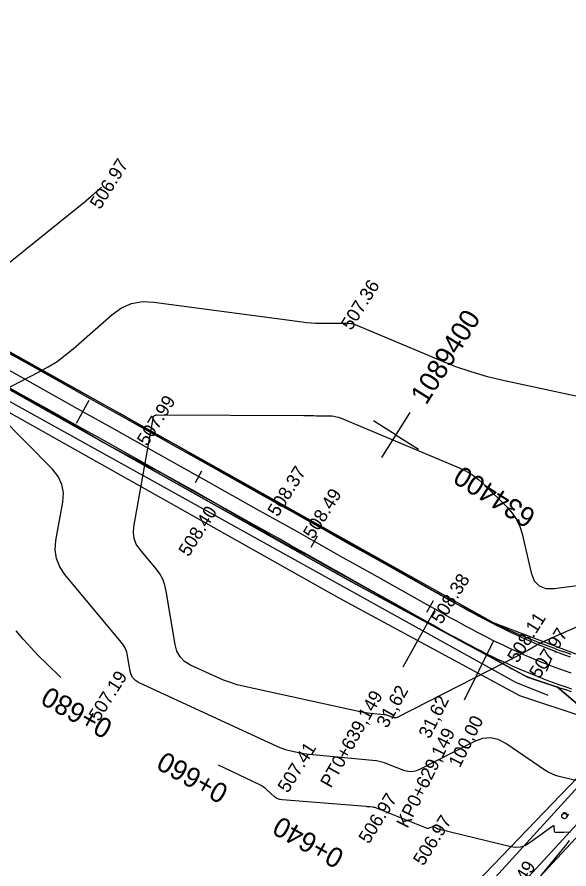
# Model space of a CAD drawing. Extents: x -636600 to -628587, y -1090963 to -1085869.
# Drawn here: x -629764.9 to -629681.7, y -1090120.7 to -1089992.4 of the extents above; entities that cross this region are included whole.
import ezdxf

# ---------------------------------------------------------------- set-up
doc = ezdxf.new("R2010")
doc.units = 0
for name, color, linetype in [('01_PARCELY_NÁVRH_PC', 7, 'Continuous'), ('06_ÚSES_IP_NAVRH', 7, 'Continuous'), ('42', 7, 'Continuous'), ('43', 7, 'Continuous'), ('Ex_Major Contours', 7, 'Continuous'), ('Ex_Minor Contours', 7, 'Continuous'), ('HEKTOMETRY100', 7, 'Continuous'), ('HEKTOMETRY20', 7, 'Continuous'), ('HL_BODY', 7, 'Continuous'), ('koty_vše', 7, 'Continuous'), ('POLOMERY', 7, 'Continuous'), ('situace_osa', 7, 'Continuous'), ('situace_těleso', 7, 'Continuous'), ('situace_vozovka', 7, 'Continuous'), ('síť křížků', 7, 'Continuous')]:
    doc.layers.add(name, color=color, linetype=linetype)

msp = doc.modelspace()

# ---------------------------------------------------------------- linework, layer by layer
at = {"layer": '01_PARCELY_NÁVRH_PC'}
for points in [[(-629590.44, -1089927.9), (-629610.34, -1089962.86), (-629611.05, -1089962.47), (-629613.94, -1089967.55), (-629651.31, -1090060.76), (-629656.7, -1090071.62), (-629663.92, -1090084.26), (-629669.51, -1090092.1), (-629671.7, -1090096.43), (-629679.1, -1090105.56), (-629740.1, -1090168.89), (-629745.82, -1090175.94), (-629753.08, -1090187.33), (-629759.69, -1090209.29), (-629763.83, -1090224.9)], [(-629757.08, -1090224.9), (-629756.4, -1090222.95), (-629754.36, -1090212.07), (-629743.98, -1090191.89), (-629738.43, -1090182.38), (-629727.31, -1090166.03), (-629671.82, -1090106.56), (-629662.5, -1090094.94), (-629652.06, -1090078.29), (-629645.47, -1090064.84), (-629624.55, -1090013.22), (-629617.14, -1089992.88), (-629607.22, -1089968.87), (-629597.44, -1089950.1), (-629584.51, -1089927.9)], [(-629847.27, -1090002.89), (-629714.93, -1090077.19), (-629687.95, -1090091.78), (-629683.43, -1090093.29), (-629680.05, -1090096.13), (-629678.2, -1090100.3), (-629678.37, -1090104.71), (-629671.7, -1090096.43), (-629669.51, -1090092.1), (-629668.44, -1090090.6), (-629674.53, -1090090.62), (-629693.09, -1090083.59), (-629847.27, -1089997.35)], [(-629847.27, -1090006.33), (-629716.38, -1090079.82), (-629689.14, -1090094.54), (-629679.3, -1090097.83), (-629680.05, -1090096.13), (-629683.43, -1090093.29), (-629687.95, -1090091.78), (-629714.93, -1090077.19), (-629847.27, -1090002.89)]]:
    msp.add_lwpolyline(points, dxfattribs=at)
at = {"layer": '06_ÚSES_IP_NAVRH'}
msp.add_lwpolyline([(-629684.85, -1090094.55), (-629689.69, -1090092.6), (-629772.39, -1090046.76), (-629847.27, -1090004.61)], dxfattribs=at)
at = {"layer": '42'}
for p, q in [((-629707.87, -1090138.35), (-629674.34, -1090101.71)), ((-629705.08, -1090140.65), (-629671.28, -1090103.86))]:
    msp.add_line(p, q, dxfattribs=at)
at = {"layer": '43'}
for p, q in [((-629682, -1090112.83), (-629681.74, -1090112.41)), ((-629682.05, -1090112.92), (-629682, -1090112.83))]:
    msp.add_line(p, q, dxfattribs=at)
msp.add_circle((-629682.39, -1090112.7), 0.4, dxfattribs=at)
msp.add_arc((-629682.34, -1090112.62), 0.4, 317.5323, 155.0179, dxfattribs=at)
at = {"layer": 'Ex_Major Contours'}
for points in [[(-629767.09, -1090048.68), (-629761.54, -1090045.82), (-629760.18, -1090045.06), (-629758.87, -1090044.23), (-629757.62, -1090043.32), (-629756.42, -1090042.33), (-629750.58, -1090037.21), (-629749.16, -1090036.19), (-629747.63, -1090035.53), (-629746, -1090035.24), (-629744.25, -1090035.3), (-629721.91, -1090038.3), (-629721.24, -1090038.38), (-629720.58, -1090038.44), (-629719.91, -1090038.47), (-629719.24, -1090038.49), (-629715.43, -1090038.5), (-629715.33, -1090038.5), (-629715.22, -1090038.5), (-629715.12, -1090038.5), (-629715.01, -1090038.5), (-629714.59, -1090038.51), (-629714.49, -1090038.51), (-629714.39, -1090038.53), (-629714.29, -1090038.55), (-629714.19, -1090038.59), (-629701.02, -1090044.12), (-629698.78, -1090045), (-629696.5, -1090045.78), (-629694.19, -1090046.45), (-629691.85, -1090047.01), (-629678.57, -1090049.89)], [(-629680.26, -1090107.45), (-629683.18, -1090106.73), (-629683.74, -1090106.57), (-629684.29, -1090106.35), (-629684.81, -1090106.09), (-629685.32, -1090105.78), (-629691.19, -1090101.77), (-629692.35, -1090101.17), (-629693.52, -1090100.92), (-629694.72, -1090101.02), (-629695.94, -1090101.47), (-629704.32, -1090105.74), (-629704.88, -1090105.96), (-629705.44, -1090106.05), (-629706.01, -1090106.01), (-629706.59, -1090105.84), (-629708.91, -1090104.91), (-629709.5, -1090104.7), (-629710.09, -1090104.53), (-629710.7, -1090104.4), (-629711.32, -1090104.32), (-629720.84, -1090103.41), (-629721.24, -1090103.36), (-629721.65, -1090103.31), (-629722.05, -1090103.24), (-629722.45, -1090103.16), (-629724.05, -1090102.81), (-629724.44, -1090102.71), (-629724.83, -1090102.59), (-629725.21, -1090102.45), (-629725.59, -1090102.29), (-629746.58, -1090092.57), (-629747.06, -1090092.28), (-629747.44, -1090091.91), (-629747.7, -1090091.45), (-629747.85, -1090090.9), (-629748.23, -1090088.57), (-629748.36, -1090088), (-629748.56, -1090087.46), (-629748.83, -1090086.96), (-629749.18, -1090086.49), (-629757.68, -1090076.32), (-629758.46, -1090075.16), (-629758.95, -1090073.91), (-629759.14, -1090072.59), (-629759.03, -1090071.19), (-629758, -1090065.43), (-629757.9, -1090064.04), (-629758.13, -1090062.75), (-629758.67, -1090061.56), (-629759.55, -1090060.48), (-629767.66, -1090052.32)]]:
    msp.add_lwpolyline(points, dxfattribs=at)
at = {"layer": 'Ex_Minor Contours'}
for points in [[(-629772.71, -1090034.67), (-629755.35, -1090020.73), (-629754.94, -1090020.39), (-629754.53, -1090020.05), (-629754.12, -1090019.71), (-629753.72, -1090019.36), (-629752.15, -1090017.99)], [(-629679.2, -1090083.64), (-629685.47, -1090086.41), (-629685.79, -1090086.56), (-629686.1, -1090086.71), (-629686.41, -1090086.87), (-629686.71, -1090087.05), (-629687.9, -1090087.75), (-629688.2, -1090087.93), (-629688.51, -1090088.1), (-629688.81, -1090088.26), (-629689.12, -1090088.42), (-629707.6, -1090097.85), (-629707.76, -1090097.91), (-629707.91, -1090097.93), (-629708.07, -1090097.92), (-629708.23, -1090097.87), (-629708.87, -1090097.62), (-629709.03, -1090097.56), (-629709.2, -1090097.51), (-629709.37, -1090097.48), (-629709.54, -1090097.45), (-629711.59, -1090097.26), (-629711.99, -1090097.21), (-629712.39, -1090097.16), (-629712.79, -1090097.09), (-629713.18, -1090097.01), (-629730.62, -1090093.19), (-629731.69, -1090092.93), (-629732.73, -1090092.61), (-629733.75, -1090092.24), (-629734.76, -1090091.8), (-629738.74, -1090089.96), (-629739.63, -1090089.42), (-629740.32, -1090088.73), (-629740.8, -1090087.88), (-629741.08, -1090086.88), (-629742.39, -1090078.84), (-629742.6, -1090077.92), (-629742.93, -1090077.05), (-629743.37, -1090076.23), (-629743.93, -1090075.46), (-629746.4, -1090072.51), (-629746.92, -1090071.75), (-629747.24, -1090070.93), (-629747.36, -1090070.06), (-629747.29, -1090069.14), (-629744.3, -1090052.52), (-629744.29, -1090052.47), (-629744.27, -1090052.44), (-629744.24, -1090052.41), (-629744.19, -1090052.39), (-629744.01, -1090052.33), (-629743.97, -1090052.31), (-629743.92, -1090052.3), (-629743.87, -1090052.3), (-629743.83, -1090052.3), (-629721.65, -1090052.4), (-629721.18, -1090052.4), (-629720.71, -1090052.4), (-629720.23, -1090052.4), (-629719.76, -1090052.41), (-629717.86, -1090052.41), (-629717.4, -1090052.44), (-629716.94, -1090052.51), (-629716.48, -1090052.62), (-629716.04, -1090052.78), (-629698.34, -1090060.22), (-629697.27, -1090060.73), (-629696.26, -1090061.33), (-629695.31, -1090062.03), (-629694.43, -1090062.83), (-629691.02, -1090066.2), (-629690.24, -1090067.08), (-629689.61, -1090068.04), (-629689.12, -1090069.09), (-629688.77, -1090070.21), (-629687.38, -1090076.08), (-629686.92, -1090077.26), (-629686.2, -1090078.04), (-629685.21, -1090078.44), (-629683.95, -1090078.45), (-629670.43, -1090076.66)], [(-629758.31, -1090091.84), (-629760.47, -1090089.74), (-629761.66, -1090088.56), (-629762.81, -1090087.34), (-629763.93, -1090086.1), (-629765.02, -1090084.83)], [(-629681.49, -1090115.13), (-629682.46, -1090115.16), (-629682.6, -1090115.16), (-629682.74, -1090115.17), (-629682.89, -1090115.17), (-629683.03, -1090115.17), (-629683.61, -1090115.18), (-629683.73, -1090115.17), (-629683.82, -1090115.12), (-629683.87, -1090115.03), (-629683.9, -1090114.91), (-629683.92, -1090114.35), (-629683.94, -1090114.24), (-629683.98, -1090114.19), (-629684.05, -1090114.18), (-629684.15, -1090114.24), (-629687.71, -1090116.8), (-629688.36, -1090117.17), (-629689.03, -1090117.38), (-629689.74, -1090117.44), (-629690.48, -1090117.33), (-629701.4, -1090114.67), (-629701.48, -1090114.64), (-629701.57, -1090114.61), (-629701.65, -1090114.57), (-629701.72, -1090114.52), (-629702.02, -1090114.32), (-629702.1, -1090114.28), (-629702.17, -1090114.26), (-629702.25, -1090114.27), (-629702.33, -1090114.3), (-629702.76, -1090114.52), (-629702.86, -1090114.56), (-629702.95, -1090114.57), (-629703.05, -1090114.56), (-629703.16, -1090114.53), (-629710.71, -1090111.5), (-629710.83, -1090111.45), (-629710.95, -1090111.42), (-629711.08, -1090111.39), (-629711.21, -1090111.37), (-629711.73, -1090111.32), (-629711.86, -1090111.31), (-629711.99, -1090111.3), (-629712.12, -1090111.29), (-629712.25, -1090111.28), (-629724.92, -1090110.28), (-629725.26, -1090110.22), (-629725.58, -1090110.11), (-629725.87, -1090109.95), (-629726.14, -1090109.74), (-629727.17, -1090108.78), (-629727.44, -1090108.55), (-629727.72, -1090108.34), (-629728.01, -1090108.16), (-629728.32, -1090107.99), (-629734.53, -1090105.02)], [(-629680.94, -1090125.5), (-629682.58, -1090124.35), (-629682.93, -1090124.11), (-629683.29, -1090123.87), (-629683.65, -1090123.64), (-629684.02, -1090123.41), (-629685.49, -1090122.51), (-629685.78, -1090122.27), (-629685.9, -1090122.01), (-629685.87, -1090121.72), (-629685.68, -1090121.4), (-629681.97, -1090116.87), (-629681.85, -1090116.71), (-629681.74, -1090116.55), (-629681.64, -1090116.38)]]:
    msp.add_lwpolyline(points, dxfattribs=at)
at = {"layer": 'HEKTOMETRY100'}
msp.add_lwpolyline([(-629755.95, -1090053.56), (-629754, -1090050.07)], dxfattribs=at)
at = {"layer": 'HEKTOMETRY20'}
for points in [[(-629738.01, -1090062.46), (-629737.03, -1090060.72)], [(-629720.56, -1090072.23), (-629719.58, -1090070.49)], [(-629703.11, -1090082), (-629702.13, -1090080.26)], [(-629685.06, -1090090.9), (-629684.34, -1090089.04)]]:
    msp.add_lwpolyline(points, dxfattribs=at)
at = {"layer": 'HL_BODY'}
for points in [[(-629701.88, -1090081.55), (-629706.76, -1090090.27)], [(-629693.07, -1090086.29), (-629697.52, -1090095.24)]]:
    msp.add_lwpolyline(points, dxfattribs=at)
at = {"layer": 'POLOMERY'}
for points in [[(-629701.88, -1090081.55), (-629706.76, -1090090.27)], [(-629693.07, -1090086.29), (-629697.52, -1090095.24)]]:
    msp.add_lwpolyline(points, dxfattribs=at)
at = {"layer": 'situace_osa'}
msp.add_lwpolyline([(-629681.39, -1090091.19), (-629682.24, -1090090.89), (-629683.09, -1090090.58), (-629683.94, -1090090.26), (-629684.7, -1090089.97), (-629684.79, -1090089.94), (-629685.63, -1090089.61), (-629686.47, -1090089.27), (-629687.31, -1090088.92), (-629688.14, -1090088.57), (-629688.97, -1090088.21), (-629689.32, -1090088.05), (-629689.8, -1090087.84), (-629690.62, -1090087.46), (-629691.44, -1090087.08), (-629692.26, -1090086.68), (-629693.07, -1090086.29), (-629693.83, -1090085.9), (-629693.89, -1090085.88), (-629694.69, -1090085.46), (-629695.5, -1090085.04), (-629696.3, -1090084.62), (-629697.1, -1090084.19), (-629697.9, -1090083.75), (-629698.25, -1090083.56), (-629698.7, -1090083.32), (-629699.5, -1090082.88), (-629700.29, -1090082.43), (-629701.08, -1090081.99), (-629701.88, -1090081.55), (-629702.62, -1090081.13), (-629706.98, -1090078.69), (-629711.35, -1090076.25), (-629715.71, -1090073.8), (-629720.07, -1090071.36), (-629722.64, -1090069.92), (-629724.43, -1090068.92), (-629728.8, -1090066.47), (-629733.16, -1090064.03), (-629737.52, -1090061.59), (-629741.88, -1090059.15), (-629746.25, -1090056.7), (-629750.61, -1090054.26), (-629754.97, -1090051.82), (-629759.33, -1090049.38), (-629763.7, -1090046.93), (-629768.06, -1090044.49)], dxfattribs=at)
at = {"layer": 'situace_těleso'}
for points in [[(-629681.35, -1090088.38), (-629682.18, -1090088.09), (-629683.01, -1090087.8), (-629683.76, -1090087.52), (-629683.84, -1090087.49), (-629684.66, -1090087.17), (-629685.48, -1090086.85), (-629686.31, -1090086.54), (-629687.13, -1090086.22), (-629687.96, -1090085.9), (-629688.3, -1090085.76), (-629688.78, -1090085.57), (-629689.59, -1090085.23), (-629690.39, -1090084.86), (-629691.2, -1090084.49), (-629692, -1090084.12), (-629692.75, -1090083.76), (-629692.8, -1090083.73), (-629693.6, -1090083.34), (-629694.4, -1090082.94), (-629695.19, -1090082.54), (-629695.99, -1090082.13), (-629696.79, -1090081.71), (-629697.13, -1090081.53), (-629697.58, -1090081.29), (-629698.38, -1090080.87), (-629699.18, -1090080.44), (-629699.98, -1090080.01), (-629700.77, -1090079.58), (-629701.51, -1090079.15), (-629705.85, -1090076.67), (-629710.19, -1090074.18), (-629714.53, -1090071.7), (-629718.9, -1090069.27), (-629721.49, -1090067.88), (-629723.28, -1090066.85), (-629727.66, -1090064.45), (-629732.02, -1090062), (-629736.35, -1090059.5), (-629740.68, -1090056.99), (-629745.06, -1090054.58), (-629749.4, -1090052.1), (-629753.76, -1090049.66), (-629758.15, -1090047.26), (-629762.54, -1090044.87), (-629766.93, -1090042.47)], [(-629769.17, -1090046.47), (-629764.84, -1090048.97), (-629760.47, -1090051.4), (-629756.12, -1090053.87), (-629751.84, -1090056.46), (-629747.44, -1090058.83), (-629742.99, -1090061.12), (-629738.65, -1090063.6), (-629734.26, -1090066.01), (-629729.93, -1090068.5), (-629725.62, -1090071.04), (-629723.84, -1090072.07), (-629721.19, -1090073.35), (-629716.83, -1090075.82), (-629712.45, -1090078.22), (-629708.11, -1090080.7), (-629703.77, -1090083.19), (-629703.04, -1090083.62), (-629702.24, -1090084.05), (-629701.43, -1090084.48), (-629700.62, -1090084.91), (-629699.81, -1090085.33), (-629699.35, -1090085.57), (-629699, -1090085.76), (-629698.18, -1090086.18), (-629697.37, -1090086.61), (-629696.56, -1090087.06), (-629695.75, -1090087.5), (-629694.93, -1090087.94), (-629694.88, -1090087.97), (-629694.12, -1090088.4), (-629693.31, -1090088.85), (-629692.49, -1090089.29), (-629691.68, -1090089.75), (-629690.87, -1090090.2), (-629690.39, -1090090.46), (-629690.05, -1090090.65), (-629689.22, -1090091.08), (-629688.39, -1090091.51), (-629687.53, -1090091.87), (-629686.66, -1090092.18), (-629685.78, -1090092.49), (-629685.69, -1090092.53), (-629684.9, -1090092.8), (-629684.01, -1090093.09), (-629683.13, -1090093.38), (-629682.24, -1090093.66), (-629681.35, -1090093.93)]]:
    msp.add_lwpolyline(points, dxfattribs=at)
at = {"layer": 'situace_vozovka'}
for points in [[(-629681.48, -1090088.77), (-629682.32, -1090088.47), (-629683.15, -1090088.16), (-629683.89, -1090087.87), (-629683.97, -1090087.84), (-629684.8, -1090087.52), (-629685.62, -1090087.18), (-629686.44, -1090086.85), (-629687.25, -1090086.5), (-629688.06, -1090086.15), (-629688.4, -1090086), (-629688.87, -1090085.79), (-629689.68, -1090085.42), (-629690.48, -1090085.04), (-629691.28, -1090084.66), (-629692.07, -1090084.27), (-629692.82, -1090083.9), (-629692.87, -1090083.87), (-629693.66, -1090083.47), (-629694.45, -1090083.05), (-629695.24, -1090082.63), (-629696.03, -1090082.21), (-629696.82, -1090081.78), (-629697.17, -1090081.59), (-629697.61, -1090081.35), (-629698.4, -1090080.91), (-629699.19, -1090080.47), (-629699.99, -1090080.03), (-629700.78, -1090079.58), (-629701.52, -1090079.17), (-629705.88, -1090076.73), (-629710.25, -1090074.28), (-629714.61, -1090071.84), (-629718.97, -1090069.4), (-629721.54, -1090067.96), (-629723.33, -1090066.95), (-629727.7, -1090064.51), (-629732.06, -1090062.07), (-629736.42, -1090059.63), (-629740.78, -1090057.18), (-629745.15, -1090054.74), (-629749.51, -1090052.3), (-629753.87, -1090049.86), (-629758.24, -1090047.41), (-629762.6, -1090044.97), (-629766.96, -1090042.53)], [(-629681.25, -1090093.61), (-629682.12, -1090093.31), (-629683, -1090093), (-629683.87, -1090092.69), (-629684.73, -1090092.37), (-629685.51, -1090092.07), (-629685.6, -1090092.04), (-629686.46, -1090091.7), (-629687.32, -1090091.35), (-629688.18, -1090091), (-629689.03, -1090090.63), (-629689.88, -1090090.26), (-629690.23, -1090090.11), (-629690.72, -1090089.89), (-629691.57, -1090089.5), (-629692.41, -1090089.11), (-629693.24, -1090088.71), (-629694.07, -1090088.3), (-629694.85, -1090087.91), (-629694.9, -1090087.89), (-629695.73, -1090087.46), (-629696.55, -1090087.04), (-629697.36, -1090086.6), (-629698.17, -1090086.17), (-629698.98, -1090085.73), (-629699.33, -1090085.54), (-629699.79, -1090085.29), (-629700.59, -1090084.84), (-629701.39, -1090084.4), (-629702.18, -1090083.95), (-629702.98, -1090083.51), (-629703.72, -1090083.09), (-629708.08, -1090080.65), (-629712.44, -1090078.21), (-629716.81, -1090075.77), (-629721.17, -1090073.32), (-629723.74, -1090071.89), (-629725.53, -1090070.88), (-629729.9, -1090068.44), (-629734.26, -1090066), (-629738.62, -1090063.55), (-629742.98, -1090061.11), (-629747.35, -1090058.67), (-629751.71, -1090056.22), (-629756.07, -1090053.78), (-629760.43, -1090051.34), (-629764.8, -1090048.9), (-629769.16, -1090046.45)]]:
    msp.add_lwpolyline(points, dxfattribs=at)
at = {"layer": 'síť křížků'}
for p, q in [((-629709.89, -1090058.72), (-629705.63, -1090051.95)), ((-629707.76, -1090055.33), (-629711.14, -1090053.2)), ((-629707.76, -1090055.33), (-629704.37, -1090057.46))]:
    msp.add_line(p, q, dxfattribs=at)

# ---------------------------------------------------------------- texts
at = {"layer": 'HEKTOMETRY20'}
for s, p in [('0+680', (-629750.26, -1090098.58)), ('0+660', (-629732.81, -1090108.35)), ('0+640', (-629715.36, -1090118.12))]:
    msp.add_text(s, height=3, rotation=150.755, dxfattribs=at).set_placement(p)
at = {"layer": 'HL_BODY'}
for s, rotation, p in [('PT0+639,149', 60.755, (-629717.57, -1090108.6)), ('KP0+629,149', 63.6198, (-629706.03, -1090114.66))]:
    msp.add_text(s, height=2, rotation=rotation, dxfattribs=at).set_placement(p)
at = {"layer": 'koty_vše'}
for s, p in [('506.97', (-629752.37, -1090021.47)), ('507.36', (-629714.52, -1090039.68)), ('507.99', (-629745.27, -1090057.1)), ('508.37', (-629725.59, -1090067.76)), ('508.49', (-629720.23, -1090071.13)), ('508.40', (-629739.01, -1090073.76)), ('508.38', (-629700.92, -1090083.94)), ('508.11', (-629689.45, -1090089.77)), ('507.97', (-629686.14, -1090092.13)), ('507.19', (-629752.55, -1090098.58)), ('507.41', (-629724.07, -1090109.34)), ('506.97', (-629711.87, -1090117.01)), ('506.97', (-629703.64, -1090120.32)), ('506.49', (-629690.98, -1090127.18))]:
    msp.add_text(s, height=2, rotation=57.8371, dxfattribs=at).set_placement(p)
at = {"layer": 'POLOMERY'}
for s, rotation, p in [('31,62', 60.755, (-629709.11, -1090099.59)), ('31,62', 63.6198, (-629702.69, -1090101.18)), ('100,00', 63.6198, (-629698.16, -1090105.55))]:
    msp.add_text(s, height=2, rotation=rotation, dxfattribs=at).set_placement(p)
at = {"layer": 'síť křížků'}
for s, rotation, p in [('1089400', 57.8371, (-629703.22, -1090050.93)), ('634400', 147.8371, (-629686.47, -1090066.95))]:
    msp.add_text(s, height=3, rotation=rotation, dxfattribs=at).set_placement(p)

doc.saveas('drawing.dxf')
